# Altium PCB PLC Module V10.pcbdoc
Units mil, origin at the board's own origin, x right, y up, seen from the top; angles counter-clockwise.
Board outline 1414 x 3239 mil, 2 copper layers (Top Layer, Bottom Layer); 81 components, 51 nets, 211 pads, 22 vias.
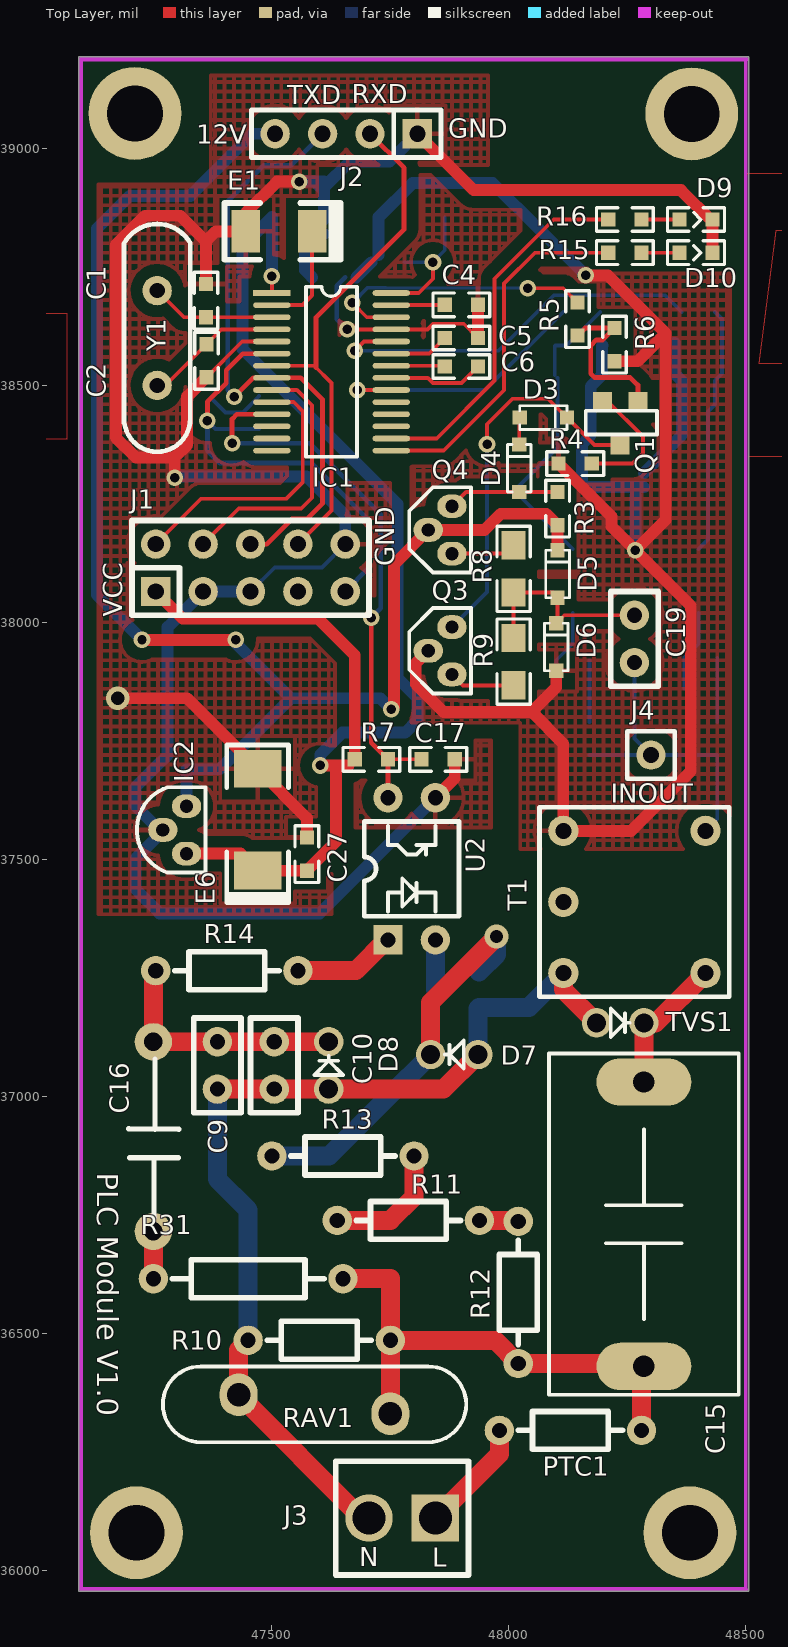
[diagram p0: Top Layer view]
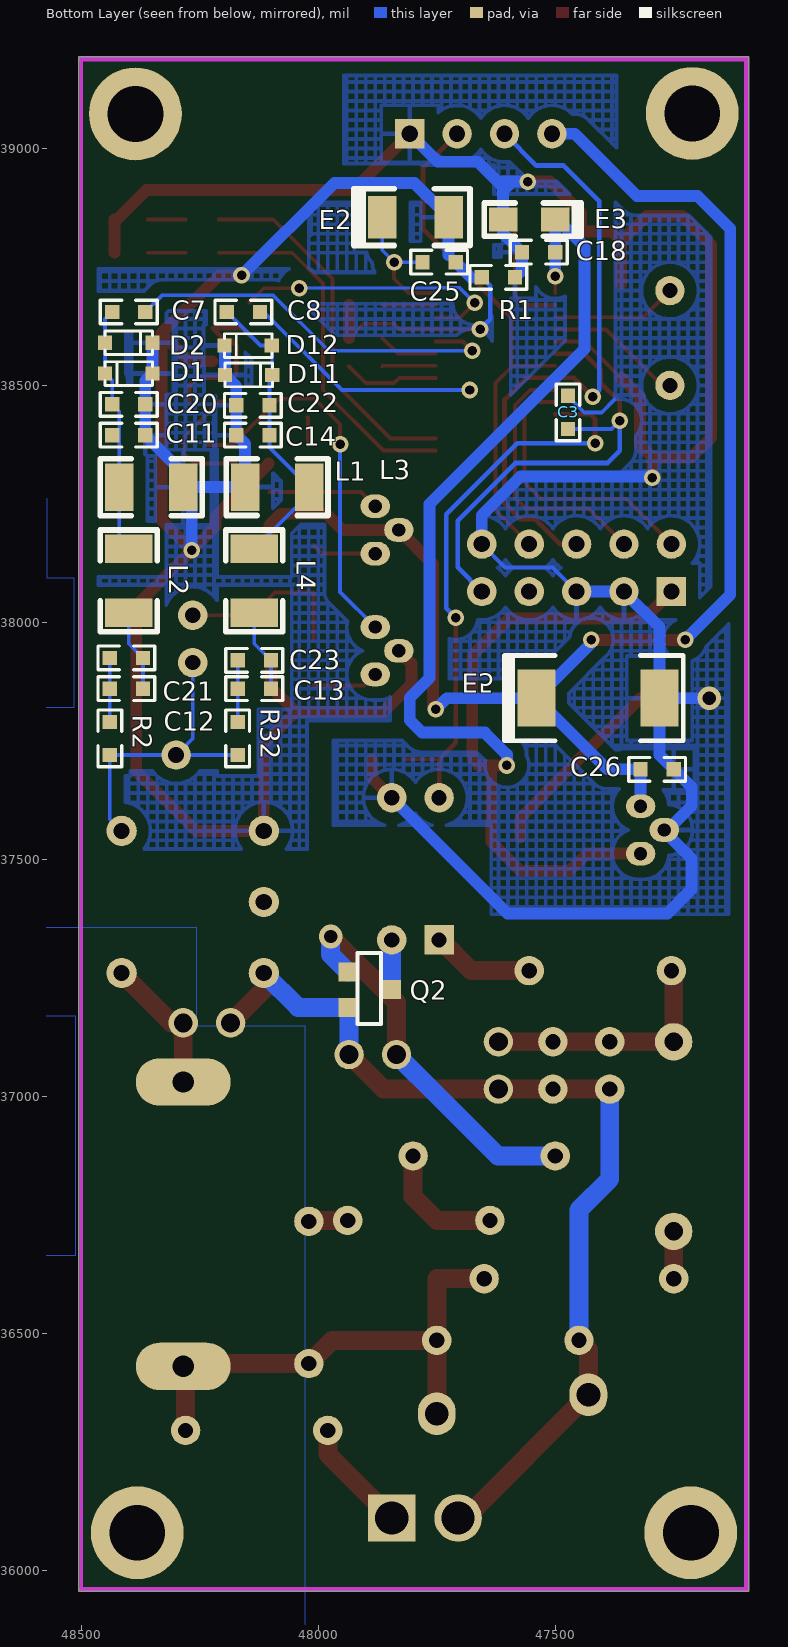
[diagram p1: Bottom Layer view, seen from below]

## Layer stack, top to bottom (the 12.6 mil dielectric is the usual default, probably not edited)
Top Layer: signal copper 1.4
Dielectric: core 12.6, FR-4, Dk 4.8
Bottom Layer: signal copper 1.4

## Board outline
47092,35955 48506,35955 48506,39194 47092,39194

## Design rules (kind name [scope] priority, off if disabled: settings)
Clearance [All] p1: gap=8
PolygonConnect [All] p1: connectstyle=Relief reliefconductorwidth=10 reliefentries=4 polygonreliefangle="90 Angle"
RoutingVias [All] p1: holewidth=28 width=50 viastyle="Through Hole" minholewidth=28 minwidth=50 maxholewidth=28 maxwidth=50
SilkscreenOverComponentPads [All] p1: minsilkscreentomaskgap=10
SolderMaskExpansion [All] p1: expansion=4
Width [All] p1: maxlimit=40 minlimit=8 preferedwidth=8
27 further rules are at their usual default settings.

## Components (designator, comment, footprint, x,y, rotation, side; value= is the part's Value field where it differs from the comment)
C1 "12p" 0603#1 47361,38644 r90 top
C2 "12p" 0603#1 47362,38587 r270 top
C3 "104" 0603#1 47473,38408 r90 bottom
C4 "0.1uF" 0603#1 47865,38670 r0 top
C5 "0.1uF" 0603#1 47865,38600 r0 top
C6 "0.1uF" 0603#1 47935,38540 r180 top
C7 "0.1uF" 0603#1 48365,38655 r0 bottom
C8 "0.1uF" 0603#1 48123,38655 r0 bottom
C9 "0.1uF" RAD0.1 47385,37015 r90 top
C10 "0.1uF" RAD0.1 47505,37015 r90 top
C11 "10nF" 0603#1 48365,38395 r0 bottom
C12 "680pF" 0603#1 48440,37860 r180 bottom
C13 "22nF" 0603#1 48170,37860 r180 bottom
C14 "100nF" 0603#1 48173,38395 r180 bottom
C15 "0.22u/275V" RAD-0.6 48285,36730 r90 top
C16 "0.01u/275V" RAD-0.4 47250,36715 r90 top
C17 "0.01uF" 0603#1 47886,37711 r180 top
C18 "0.1uF" 0603#1 47500,38781 r0 bottom
C19 "0.33uF" RAD0.1 48265,38015 r270 top
C20 "12pF" 0603#1 48365,38460 r0 bottom
C21 "12pF" 0603#1 48440,37925 r180 bottom
C22 "12pF" 0603#1 48173,38458 r180 bottom
C23 "12pF" 0603#1 48170,37920 r180 bottom
C25 "0.1uF" 0603#1 47780,38760 r180 bottom
C26 "104" 0603#1 47320,37690 r180 bottom
C27 "104" 0603#1 47574,37476 r90 top
D1 "1N4148" SOD323 48350,38525 r0 bottom
D2 "1N4148" SOD323 48450,38590 r180 bottom
D3 "IN4148" SOD323 48023,38432 r0 top
D4 "IN4148" SOD323 48022,38275 r90 top
D5 "IN4148" SOD323 48103,38052 r90 top
D6 "IN4148" SOD323 48100,37898 r90 top
D7 "1N4007" DIODE0.1 47935,37088 r180 top
D8 "5.1V" DIODE0.1 47620,37015 r90 top
D9 "TX" 0603-D 48360,38850 r0 top
D10 "RX" 0603-D 48360,38780 r0 top
D11 "1N4148" SOD323 48197,38522 r180 bottom
D12 "1N4148" SOD323 48098,38584 r0 bottom
E1 "47uF/16V" 3528(B) 47585,38825 r180 top
E2 "47uF/16V" 3528(B) 47865,38855 r180 bottom
E3 "10uF/16V" 3216(A) 47500,38850 r0 bottom
E5 "100uF/25V" 7343(D) 47540,37840 r180 bottom
E6 "100uF/16V" 6032(C) 47470,37476 r90 top
IC1 "SH99F01" TSSOP28 47500,38695 r0 top
IC2 "78L05" TO-92B 47320,37512 r90 top
J1 "JTAG" IDC10 47255,38065 r0 top
J2 "CON4" SIP4 47807,39031 r180 top
J3 "AC220V" SIP2W 47845,36110 r180 top
J4 "INOUT" SIP1 48300,37720 r0 top
L1 "33uH" 1210 48285,38285 r0 bottom
L2 "470uH" 1210 48400,38155 r270 bottom
L3 "100uH" 1210 48154.52,38285.48 r180 bottom
L4 "470uH" 1210 48135,38155 r270 bottom
PTC1 "C250-120U" AXIAL0.3 48280,36295 r180 top
Q1 "9014" SOT323-Q 48235,38374 r180 top
Q2 "9014" SOT323-Q 47845,37225 r270 bottom
Q3 "2SA1020" TO-92A 47880,37890 r90 top
Q4 "2SC2655" TO-92A 47880,38145 r90 top
R1 "0" 0603#1 47585,38728 r0 bottom
R2 "470" 0603#1 48440,37790 r270 bottom
R3 "470" 0603#1 48103,38205 r90 top
R4 "100" 0603#1 48175,38335 r180 top
R5 "100" 0603#2 48145,38605 r90 bottom
R6 "10K" 0603#1 48223,38621 r270 top
R7 "10K" 0603#1 47745,37711 r180 top
R8 "1/0.5W" 0805 48010,38163 r270 top
R9 "1/0.5W" 0805 48010,37967 r270 top
R10 "1M/0.25W" AXIAL0.3 47750,36485 r180 top
R11 "470K/0.25W" AXIAL0.3 47938,36738 r180 top
R12 "470K/0.25W" AXIAL0.3 48020,36736 r270 top
R13 "470K/0.25W" AXIAL0.3 47800,36874 r180 top
R14 "2K" AXIAL0.3 47255,37265 r0 top
R15 "1K" 0603#1 48210,38780 r0 top
R16 "1K" 0603#1 48280,38850 r180 top
R31 "1K" AXIAL0.4 47250,36615 r0 top
R32 "470" 0603#1 48170,37790 r270 bottom
RAV1 "14D471K" ZNR 47590,36350 r0 top
T1 "15:10 (425uH)" TRANS5 48415,37260 r90 top
TVS1 "P6KE22CA" DIODE0.1 48185,37155 r0 top
U2 "NEC2501" TLP 47745,37330 r0 top
Y1 "16M" CRY2 47258,38500 r90 top

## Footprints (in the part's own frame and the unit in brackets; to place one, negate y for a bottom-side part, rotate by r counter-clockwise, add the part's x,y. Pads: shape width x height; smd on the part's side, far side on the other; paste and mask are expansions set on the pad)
0603#1 [mil]
  rect 30x30 smd: 1(0,0) 2(70,0)
  silkscreen extent -25,-25 95,25
0603#2 [mil]
  rect 30x30 smd far side: 1(0,0) 2(70,0)
0603-D [mil]
  rect 30x30 smd: A(0,0) K(70,0)
  silkscreen extent -25,-25 95,25
0805 [mil]
  rect 60x50 smd: 1(0,0) 2(100,0)
  silkscreen extent -40,-35 140,35
1210 [mil]
  rect 60x100 smd: 1(0,0) 2(135,0)
  silkscreen extent -40,-60 175,60
3216(A) [mil]
  rect 60x50 smd: 1(0,0) 2(110,0)
  silkscreen extent -55,-35 150,35
3528(B) [mil]
  rect 60x90 smd: 1(0,0) 2(140,0)
  silkscreen extent -60,-60 185,60
6032(C) [mil]
  rect 80x100 smd: 1(0,0) 2(215,0)
  silkscreen extent -67,-65 265,65
7343(D) [mil]
  rect 80x120 smd: 1(0,0) 2(260,0)
  silkscreen extent -67,-90 310,90
AXIAL0.3 [mil]
  round 62 hole 32: 1(0,0) 2(300,0)
  silkscreen extent 40,-40 260,40
AXIAL0.4 [mil]
  round 62 hole 32: 1(0,0) 2(400,0)
  silkscreen extent 40,-40 360,40
CRY2 [mil]
  round 62 hole 32: 1(0,0) 2(200,0)
  silkscreen extent -140,-70 341,70
DIODE0.1 [mil]
  round 62 hole 40: A(0,0) K(100,0)
  silkscreen extent 30,-30 70,30
IDC10 [mil]
  rect 62x62 hole 34: 1(0,0)
  round 62 hole 34: 2(0,100) 3(100,0) 4(100,100) 5(200,0) 6(200,100) 7(300,0) 8(300,100) 9(400,0) 10(400,100)
  silkscreen extent -50,-50 450,150
RAD0.1 [mil]
  round 62 hole 32: 1(0,0) 2(100,0)
  silkscreen extent -50,-50 150,50
RAD-0.4 [mm]
  round 2 hole 1: 1(0,0) 2(10.16,0)
  silkscreen extent 0.75,-1.35 9.23,1.31
RAD-0.6 [mil]
  oval 100x200 hole 45: 1(-300,0) 2(300,0)
  silkscreen extent -360,-200 360,200
SIP1 [mil]
  round 62 hole 34: 1(0,0)
  silkscreen extent -50,-50 50,50
SIP2W [mil]
  rect 100x100 hole 70: 1(0,0)
  round 100 hole 70: 2(140,0)
  silkscreen extent -70,-120 210,120
SIP4 [mil]
  rect 62x62 hole 34: 1(0,0)
  round 62 hole 34: 2(100,0) 3(200,0) 4(300,0)
  silkscreen extent -50,-50 350,50
SOD323 [mil]
  rect 30x30 smd: A(0,0) K(100,0)
  silkscreen extent 0,-25 100,25
SOT323-Q [mil]
  rect 40x40 smd: B(-37.4,-92.52) C(0,0) E(37.4,-92.52)
  silkscreen extent -77,-73 73,-23
TLP [mil]
  rect 62x62 hole 32: A(0,0)
  round 62 hole 32: C(0,300) E(100,300) K(100,0)
  silkscreen extent -50,50 150,250
TO-92A [mil]
  oval 50x62 hole 28: B(100,0) C(50,50) E(0,0)
  silkscreen extent -40,-40 140,90
TO-92B [mil]
  oval 50x62 hole 28: 1(0,0) 2(50,50) 3(100,0)
  silkscreen extent -40,-40 140,105
TRANS5 [mil]
  round 64 hole 34: 1(0,0) 2(300,0) 3(0,300) 4(300,300) 5(150,300)
  silkscreen extent -50,-50 350,350
TSSOP28 [mm]
  rect 2x0.3 smd: 1(0,0)
  oval 2x0.3 smd: 2(0,-0.65) 3(0,-1.3) 4(0,-1.95) 5(0,-2.6) 6(0,-3.25) 7(0,-3.9) 8(0,-4.55) 9(0,-5.2) 10(0,-5.85) 11(0,-6.5) 12(0,-7.15) 13(0,-7.8) 14(0,-8.45) 15(6.4,-8.45) 16(6.4,-7.8) 17(6.4,-7.15) 18(6.4,-6.5) 19(6.4,-5.85) 20(6.4,-5.2) 21(6.4,-4.55) 22(6.4,-3.9) 23(6.4,-3.25) 24(6.4,-2.6) 25(6.4,-1.95) 26(6.4,-1.3) 27(6.4,-0.65) 28(6.4,0)
  silkscreen extent 1.83,-8.78 4.56,0.33
ZNR [mil]
  oval 80x90 hole 50: 1(-160,20) 2(160,-20)
  silkscreen extent -320,-80 320,80

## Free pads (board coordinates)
  round 196 hole 118: ""(47211,39074) ""(47214,36079) ""(48382,36079) ""(48386,39073)

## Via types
v1: diameter 35, hole 20, Top Layer to Bottom Layer, 20 vias
v2: diameter 50, hole 28, Top Layer to Bottom Layer, 2 vias

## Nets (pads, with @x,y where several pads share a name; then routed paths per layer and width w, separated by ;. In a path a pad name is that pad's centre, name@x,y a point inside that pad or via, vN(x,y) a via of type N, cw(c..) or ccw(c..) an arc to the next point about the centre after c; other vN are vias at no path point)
AGND: C4.2 C5.2 C11.1 C14.1 C20.1 C22.1 C25.2 D1.A D2.K D6.A D11.A D12.K E2.2 IC1.25 L1.1 L3.1 Q3.C R1.2 R4.2 R6.2 T1.4 | length 4698.5
  Top Layer w8: v1(47658.77,38618.23) 47828.23,38618.23 47840,38630 47905,38630 C5.2
  Top Layer w10: 48329,38551 48331,38553
  Top Layer w25: Q3.C 47803.49,37913.49 47803.49,37869.51 47859.94,37813.06 ; 47862,37811 48048,37811 ; C5.2 C4.2 ; D6.A 48100,37863 48048,37811 ; R4.2 48217,38223 48217,38202 48384,38035 48384,37686 48258,37560 T1.4 48115,37744 48048,37811 ; v1(48162,38732) 48209,38732 48331,38610 ; R6.2 48272,38551 48331,38610 ; v1(48267,38152) 48331,38216 48331,38610
  Bottom Layer w10: R1.2 47637.08,38710.08 47637.08,38639.92 v1(47658.77,38618.23)
  Bottom Layer w25: 47678,38728 C25.2 ; 47725,38775 E2.2 47797,38927 47966,38927 v1(48162,38732) ; D12.K 48197,38583 D11.A 48173,38498 C14.1 48154.52,38376.52 L3.1 48284.52,38285.48 L1.1 ; v1(48267,38152) L1.1@48267,38267 ; L1.1@48285,38315 C11.1 48365,38510 D1.A D2.K
GND: C1.2 C2.2 C3.2 C17.1 C18.2 C26.2 C27.2 D9.K D10.K E1.2 E3.2 E5.2 E6.2 IC1.5 IC2.2 J1.3 J1.5 J1.10 J2.1 R1.1 U2.E | length 5993.6
  Top Layer w8: C2.2 47437.64,38592.64 IC1.5
  Top Layer w25: v2(47175,37840) 47321,37840 E6.2 47574,37587 C27.2 ; v1(47295,38305) 47295,38348 ; C1.2 47361,38804 ; C2.2 47321.21,38476.21 47321.21,38374.21 47295,38348 ; v1(47558,38930) 47511,38930 47445,38864 E1.2 47382,38825 47361,38804 ; J2.1 47926,38912 48363,38912 D9.K@48430,38845 ; U2.E 47886,37671 C17.1 ; D10.K D9.K ; 47295,38348 47213,38348 47171,38390 47171,38797 47232,38858 47307,38858 47361,38804
  Bottom Layer w8: 47374.86,38470.21 47402.08,38443 47439,38443 47473,38477 C3.2 ; J1.5 47506,38116 47606,38116 J1.10
  Bottom Layer w25: v2(47175,37840) E5.2 ; 47212.73,37436.27 47212.73,37501.73 47268,37557 47212,37613 47212,37652 47254.26,37694.26 47280,37720 47280,37990 J1.3 J1.5 ; 47219.02,37429.98 47263,37386 47388,37386 47601,37386 U2.E ; v1@47295,38308 47573,38308 47655,38226 J1.10 ; v1(47558,38930) 47610,38930 E3.2 ; C18.2@47570,38780 47610,38820 ; C18.2 47570,38743 R1.1 ; 47591,38930 47610,38911 ; 47610,38918 47664,38972 47748,38972 J2.1
INOUT_1: C19.2 J4.1 R2.2 R32.2 T1.2 | length 649.9
  Bottom Layer w8: R32.2 R2.2 48440,37585 T1.2 ; C19.2 48265,37755 J4.1
L_1: J3.1 PTC1.2 | length 248.9
  Top Layer w40: J3.1 47980,36245 PTC1.2@47980,36303
N00005: E1.1 IC1.2 | length 228.5
  Top Layer w8: IC1.2 47564.41,38669.41 47585,38690 E1.1
N00015: D4.A Q4.B R3.2 | length 235.4
  Top Layer w8: Q4.B 47910,38275 R3.2
N00017: Q1.B R5.1 R6.1 | length 352.9
  Top Layer w10: R5.1 48161,38621 R6.1 48198,38596 48185,38596 48173,38584 48173,38524.46 48180.94,38516.52 48256.48,38516.52 48272.4,38500.6 Q1.B
N00018: D3.A D4.K | length 57.4
  Top Layer w8: D4.K 48022,38431 D3.A
N00019: D3.K Q1.C Q3.B | length 802.6
  Top Layer w8: v1(47954,38376) 47954,38418 48008,38472 48083,38472 48181,38374 Q1.C
  Bottom Layer w8: Q3.B 47954,38064 v1(47954,38376)
N00020: Q1.E R4.1 | length 268.4
  Top Layer w8: R4.1 48261,38335 48283,38357 48283,38392 48208.48,38466.52 Q1.E
N00027: C6.1 IC1.21 | length 202
  Top Layer w8: IC1.21 47829.13,38515.87 47840,38505 47900,38505 C6.1
N00028: C6.2 IC1.22 | length 113.6
  Top Layer w8: IC1.22 47863.54,38541.46 C6.2
N00029: C5.1 IC1.23 | length 126.7
  Top Layer w8: IC1.23 47832.05,38567.05 C5.1
N00031: C4.1 IC1.27 | length 112.4
  Top Layer w8: IC1.27 C4.1@47864.41,38669.41
N00032: C25.1 E2.1 IC1.28 | length 300.8
  Top Layer w8: IC1.28 47810,38695 47840,38725 v1(47840,38760)
  Bottom Layer w8: C25.1 v1(47840,38760) 47865,38785 E2.1
N00033: D10.A R15.2 | length 80
  Top Layer w8: R15.2 D10.A
N00034: Q3.E R9.2 | length 139.5
  Top Layer w8: Q3.E 47903,37867 R9.2
N00035: Q4.E R8.1 | length 137.5
  Top Layer w8: Q4.E 47992,38145 R8.1
N00036: C19.1 D5.A D6.K R8.2 R9.1 | length 416.6
  Top Layer w8: R9.1 R8.2 48092,38063 D5.A D6.K@48103,38001 ; D6.K 48117,38015 C19.1
N00037: D9.A R16.1 | length 80
  Top Layer w8: R16.1 D9.A
N00041: C8.2 C14.2 C22.2 D11.K D12.A L3.2 L4.1 | length 613.8
  Bottom Layer w8: L3.2@48019.52,38270.48 L4.1 ; L3.2 48103,38368.96 D11.K@48103,38516 ; D11.K D12.A@48097,38583 ; D12.A 48122,38584 C8.2
N00042: C7.2 C11.2 C20.2 D1.K D2.A L1.2 L2.1 | length 526.9
  Bottom Layer w8: L2.1 48420,38175 48420,38445 C20.2 48435,38510 D1.K D2.A 48450,38640 C7.2
N00044: C9.2 C10.2 C16.2 D8.K R14.1 | length 522.1
  Top Layer w40: R14.1 47250,37260 C16.2 D8.K
N00045: R14.2 U2.A | length 221
  Top Layer w40: R14.2 47677,37265 U2.A@47747,37335
N00046: C15.2 T1.1 TVS1.K | length 303.5
  Top Layer w40: C15.2 TVS1.K@48285,37160 ; TVS1.K 48310,37155 T1.1
N00048: Q2.C U2.K | length 105
  Bottom Layer w40: Q2.C U2.K
N00049: C15.1 PTC1.1 R10.1 R12.2 R31.2 RAV1.2 | length 1077.8
  Top Layer w40: R31.2 47750,36615 RAV1.2 ; R10.1 47971,36485 R12.2 48279,36436 C15.1 ; PTC1.1 C15.1@48280,36430
N00050: C13.2 C23.2 L4.2 | length 174.5
  Bottom Layer w8: C13.2 C23.2 48135,37955 L4.2
N00051: C12.2 C21.2 L2.2 | length 172.4
  Bottom Layer w8: C12.2 C21.2 48400,37955 L2.2
N00052: C16.1 R31.1 | length 100
  Top Layer w40: R31.1 C16.1
N00053: D7.K Q2.B R13.2 | length 819.9
  Top Layer w40: D7.K 47835,37198 v2(47974,37337)
  Bottom Layer w40: R13.2 47621,36874 47745,36998 D7.K ; Q2.B 47974,37298.88 v2(47974,37337)
N00054: C13.1 C23.1 R32.1 | length 130
  Bottom Layer w8: R32.1 C23.1
N00055: C12.1 C21.1 R2.1 | length 135
  Bottom Layer w8: R2.1 C21.1
N00056: R11.2 R13.1 | length 268.7
  Top Layer w40: R11.2 47750,36738 47800,36788 R13.1
N00058: R11.1 R12.1 | length 82.8
  Top Layer w40: R11.1 48018,36738 R12.1
N_1: C9.1 C10.1 D7.A D8.A J3.2 Q2.E R10.2 RAV1.1 T1.3 TVS1.A | length 2081.7
  Top Layer w40: C9.1 47862,37015 D7.A ; R10.2 47430,36465 RAV1.1 47690,36110 J3.2 ; T1.3 48115,37225 TVS1.A
  Bottom Layer w40: C9.1 47385,36825 47450,36760 R10.2 ; D7.A Q2.E@47935,37185.08 ; Q2.E 48042.6,37187.6 T1.3
OSCI_1: C1.1 IC1.3 Y1.2 | length 265
  Top Layer w8: Y1.2 47314,38644 C1.1 ; C1.1@47361.18,38643.82 IC1.3
OSCO_1: C2.1 IC1.4 Y1.1 | length 291
  Top Layer w8: Y1.1 47275,38500 47393.23,38618.23 IC1.4
P0.6_1: IC1.16 R16.2 | length 775.4
  Top Layer w8: IC1.16 47847.91,38387.91 47970,38510 47970,38725 48095,38850 R16.2
P0.7_1: IC1.15 R15.1 | length 763
  Top Layer w8: IC1.15 47862.68,38362.32 47990,38489.64 47990,38715 48055,38780 R15.1
P1.0_1: IC1.7 J1.8 J2.2 | length 1110.4
  Top Layer w8: IC1.7 47589.54,38541.46 47626,38505 47626,38236 J1.8
  Top Layer w10: 47593.09,38537.91 47593.09,38643.09 47779,38829 47779,38959 J2.2
P1.1_1: IC1.8 J1.6 J2.3 | length 1305.8
  Top Layer w10: v1(47421,38476) 47460.87,38515.87 47561.13,38515.87 47607,38470 47607,38251 47574,38218 47542,38218 47489,38165 J1.6
  Bottom Layer w10: v1(47421,38476) 47407,38490 47407,38889 47482,38964 47540,38964 J2.3
P1.2_1: IC1.9 J1.4 | length 564
  Top Layer w8: J1.4 47430,38240 47562,38240 47585,38263 47585,38458 47552.72,38490.28 IC1.9
P1.3_1: IC1.10 J1.2 | length 587.6
  Top Layer w8: J1.2 47351,38261 47531,38261 47565,38295 47565,38446 47546.32,38464.68 IC1.10
P1.4_1: C17.2 IC1.11 R7.1 U2.C | length 1207.1
  Top Layer w8: R7.1 C17.2
  Top Layer w10: v1(47416,38378) 47416,38429 47426.09,38439.09 IC1.11 ; v1(47710,38010) 47710,37746 R7.1 U2.C
  Bottom Layer w10: v1(47416,38378) 47580,38378 47730,38228 47730,38030 v1(47710,38010)
RST_1: C3.1 IC1.6 J1.9 | length 986.6
  Top Layer w10: v1(47364,38425) 47364,38465 47404,38505 47404,38532 47439.05,38567.05 IC1.6
  Bottom Layer w8: v1(47364,38425) 47381,38408 C3.1
  Bottom Layer w10: v1(47364,38425) 47364,38362 47390,38336 47584,38336 47706,38214 47706,38116 J1.9
VCC: C18.1 C27.1 E3.1 E6.1 IC1.1 IC2.1 J1.1 R7.2 | length 2929.7
  Top Layer w8: IC1.1 v1(47500,38730)
  Top Layer w25: J1.1 47312,38008 47598,38008 47675,37931 R7.2 ; IC2.1 47434,37512 E6.1 C27.1 47635,37537 47635,37698 ; v1(47602,37698) R7.2@47662,37698
  Bottom Layer w25: v1(47500,38730) 47500,38855 47438,38793 47438,38577 47765,38250 47765,37883 47807,37841 47807,37793.51 47781,37767.51 47648.51,37767.51 47602,37721 v1(47602,37698)
VHH: C26.1 D5.K E5.1 IC2.3 J2.4 Q4.C R3.1 | length 3077.4
  Top Layer w25: v1(47226,37963) v1(47424,37963) ; v1(47752,37817) 47758,37823 47758,38123 Q4.C 47949,38195 47983,38229 48079,38229 R3.1 D5.K
  Bottom Layer w25: v1(47226,37963) 47130.82,38058.18 47130.82,38830.82 47200,38900 47328,38900 47409.09,38981.09 47459,39031 J2.4 ; IC2.3 C26.1 47390,37690 E5.1 ; v1(47424,37963) 47424,37956 E5.1 ; v1(47752,37817) 47729,37840 E5.1
VIN_1: C7.1 IC1.24 | length 838.1
  Top Layer w8: v1(47675,38573) 47694.64,38592.64 IC1.24
  Bottom Layer w8: v1(47675,38573) 47978,38573 48095,38690 48330,38690 C7.1
VINCOM_1: C8.1 IC1.20 | length 574.9
  Top Layer w8: v1(47680.28,38490.28) IC1.20
  Bottom Layer w8: v1(47680.28,38490.28) 47949.72,38490.28 47950,38490 C8.1@48115,38655
VOUT_1: IC1.26 R5.2 | length 595.2
  Top Layer w8: v1(47670,38674) 47700.18,38643.82 IC1.26 ; v1(48040,38705) 48115,38705 R5.2
  Bottom Layer w8: v1(47670,38674) 47702,38706 47740.36,38706 v1(48040,38705)
pads on no net: IC1.12 IC1.13 IC1.14 IC1.17 IC1.18 IC1.19 J1.7 T1.5

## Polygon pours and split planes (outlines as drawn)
AGND on Top Layer "Top Layer-AGND" (hatched 90Degree grid 20 track 8, remove dead copper, pour order 1000): 48024,37522 48479,37522 48479,38751 48025,38751 48025,38944 47701,38944 47701,38756 47642,38756 47642,38513 47794,38513 47794,37788 48024,37788
AGND on Top Layer "Top Layer-AGND 1" (hatched 90Degree grid 20 track 8, remove dead copper, pour order 1001): 49389,37492 49389,38716 48867,38716 48867,38826 48563,38826 48527,38547 48714,38547 48680,37774 48677,37730 48906,37730 48906,37483 49387,37488
GND on Top Layer "Top Layer-GND" (hatched 90Degree grid 20 track 8, remove dead copper, pour order 1002): 46779,36913 45951,36913 45951,38444 46184,38444 46184,38652 47067,38652 47067,38386 46427,38386 46427,38050 46473,38050 46473,37750 46550,37750 46550,37208 46782,37208 46782,36915
AGND on Top Layer "Top Layer-AGND 2" (hatched 90Degree grid 20 track 8, pour order 1003): 48482,37526
GND on Top Layer "Top Layer-GND 1" (hatched 90Degree grid 20 track 8, remove dead copper, pour order 1004): 47371,39157 47371,38924 47134,38924 47134,37384 47626,37384 47626,37567 47963,37567 47963,37751 47750,37751 47750,38294 47596,38294 47596,38965 47956,38965 47956,39156 47362,39156 47362,39154 47365,39154
AGND on Top Layer "Top Layer-AGND 3" (hatched 90Degree grid 20 track 8, remove dead copper, pour order 1005): 48505,38946 48505,38351 48647,38351 48647,37805 48879,37805 48879,37539 49326,37539 49326,38771 48881,38771 48881,38892 48652,38892 48652,38947 48502,38947
AGND on Bottom Layer "Bottom Layer-AGND" (hatched 90Degree grid 20 track 8, remove dead copper, pour order 1006): 49356,38073 49081,38073 49081,38261 48573,38261 48573,38094 48516,38094 48516,37820 48650,37820 48650,37087 48870,37087 48870,36840 49358,36840 49358,38073
GND on Bottom Layer "Bottom Layer-GND" (hatched 90Degree grid 20 track 8, remove dead copper, pour order 1007): 48263,37356 49146,37356 49146,37170 48513,37170 48513,36663 48632,36663 48632,35916.13 48861,35916.13 48861,35594 48028,35594 48028,37148 48257,37148 48257,37356
GND on Bottom Layer "Bottom Layer-GND 1" (hatched 90Degree grid 20 track 8, remove dead copper, pour order 1008): 47371,39154 47946,39154 47946,38965 47629,38965 47629,38771 47594,38771 47594,38296 47750,38296 47750,37751 47968,37751 47968,37572 47635,37572 47635,37384 47134,37384 47134,38924 47371,38924
AGND on Bottom Layer "Bottom Layer-AGND 1" (hatched 90Degree grid 20 track 8, remove dead copper, pour order 1009): 48020,38859 48020,38746.27 48464,38746.27 48464,37522 48024,37522 48024,37793 47774,37793 47774,38515.87 47633,38515.87 47633,38758 47688,38758 47688,38886 48017,38886 48017,38817.29 48015.62,38817.29 48015.62,38853

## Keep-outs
Keep-Out Layer:
  lines w8: 48500,35960 48500,39190
  lines w10: 47097,39189 47097,35960 48500,35960 ; 47099,39188 48501,39188

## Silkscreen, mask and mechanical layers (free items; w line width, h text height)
Top Overlay:
  text "RXD" at 47669,39095 h40
  text "TXD" at 47533,39093 h40
  text "GND" at 47872,39023 h40
  text "12V" at 47340,39010 h40
  text "GND" at 47758,38118 h40 r90
  text "VCC" at 47184,38012 h40 r90
  text "INOUT" at 48215,37619 h40
  text "PLC Module V1.0" at 47132,36839 h45 r270
  text "N" at 47684,36008 h40
  text "L" at 47838,36007 h40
